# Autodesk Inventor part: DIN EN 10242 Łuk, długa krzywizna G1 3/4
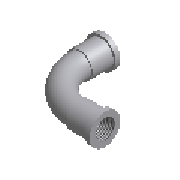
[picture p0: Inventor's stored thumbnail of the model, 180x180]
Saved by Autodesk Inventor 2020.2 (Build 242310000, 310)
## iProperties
Manager: www.cadconsulting.pl
Company: Fabian Stasiak CAD Consulting
IsCustomPart: 0
NAME: PIPING: DIN EN 10242 Long Sweep Bend G1
DATA: <meta><inlinegroups number="0" deflen="0"></inlinegroups><connections number="2"></connections><angles><a>1.57079632679489</a></angles></meta>
Created: 2014-02
Part Number: DIN EN 10242 Łuk, długa krzywizna G1 3/4
Material: Żelazo, ciągliwe
Description: Gięcie
Document SubType Name: Modeling
Standard: DIN EN 10242
Designer: F.Stasiak
Standards Organization: DIN
Language: pl-PL
Size Designation: 3/4
Categories: <MemberInstance><Categories><Category DisplayName="Rury cienko- i grubościenne" InternalName="4347fa0f-2144-441d-94cd-e3e15c92b736" Mnemonic="TUBEANDPIPE"><Cate
Density: 7.15 g/cm^3
Appearance: Częściowo polerowana
Catalog Web Link: www.expertbooks.pl
Author: F.Stasiak
Subject: Zbiór ćwiczeń. Autodesk Inventor 2020. Kurs Professional
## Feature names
1. Revolution1
2. Revolution2
3. Sweep1
## Parameters: a = 69 mm, MD = 24.117 mm, H = 35.36 mm, d0 = 24.117 mm, d1 = 35.36 mm, d2 = 5.44 mm, d3 = 22.5 mm, d26 = 90 deg, d4 = 24.117 mm, d5 = 29.92 mm, d6 = 35.36 mm, d7 = 5.44 mm, d8 = 22.5 mm, d37 = 90 deg, EE = 5.44 mm, D = 27.2 mm, z = 54 mm, d9 = 29.92 mm, d10 = 69 mm, d11 = 0, d16 = 69 mm, d17 = 15 mm, d18 = 15 mm, d19 = 27.2 mm, d91 = 15 mm, d92 = 0, d93 = 15 mm, d94 = 0, d95 = 0, Size_Designation = 7.5 mm
